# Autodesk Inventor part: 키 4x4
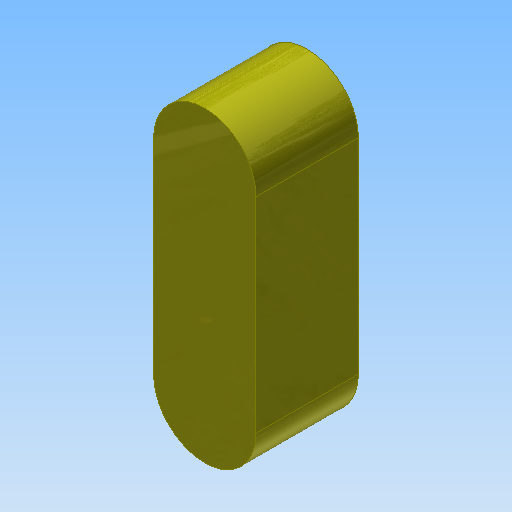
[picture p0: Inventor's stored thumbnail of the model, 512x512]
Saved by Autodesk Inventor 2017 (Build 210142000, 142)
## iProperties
Created: 2015-12
Part Number: 키 4x4
Document SubType Name: Modeling
Designer: mdu
Density: 7.86 g/cm^3
Material: 강철, 연강
Appearance: 노란색
Mass: 1.40117 g
Surface Area: 2.03398 cm^2
Volume: 0.178265 cm^3
Author: mdu
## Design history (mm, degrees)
sketch "스케치1"
  geometry: L1 (-2, -10)-(-2, -2) reference; L2 (2, -2)-(2, -10) reference; A1 r 2 centre (0, -2) between (2, -2) and (-2, -2) reference; A2 r 2 centre (0, -10) between (-2, -10) and (2, -10) reference; 1 further point
extrude "돌출1" new body sketch "스케치1" distance "d0" = 4; taper "d1" = 0 deg
node "솔리드1"
node "참조1"
